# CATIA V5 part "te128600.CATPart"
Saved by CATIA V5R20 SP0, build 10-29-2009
Part number: 1
Definition: NONE
Nomenclature: 1
Source: Unknown
Description: PART-1-DESC
Bounding box of the stored display mesh (mm): x 0 to 600, y -6 to 6, z -5.85 to 5.85
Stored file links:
  C:\Users\Utente\Desktop\IO LAVORO\3D X SITO CF\CUMSA\3D files TE\te128600.CATPart
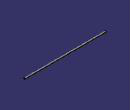
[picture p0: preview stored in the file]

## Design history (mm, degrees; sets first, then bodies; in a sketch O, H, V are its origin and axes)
Body1 "1" (main body)
  Solid1: solid without history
